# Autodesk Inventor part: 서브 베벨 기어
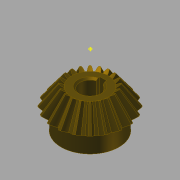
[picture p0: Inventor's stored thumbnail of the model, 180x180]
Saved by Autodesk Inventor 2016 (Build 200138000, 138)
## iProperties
Created: 2014-10
Part Number: 서브 베벨 기어
Material: 강철, 탄소
Document SubType Name: Modeling
Designer: KYOUNG IL JANG
Categories: <?xml version="1.0" encoding="UTF-16"?> <MemberInstance><Categories><FamilyTemplate><FamilyTemplateParameter ValueType="xs:double" Id="1" ObjectReferenceKey="da
Mass: 135.037 g
Surface Area: 63.6518 cm^2
Volume: 17.1585 cm^3
Density: 7.87 g/cm^3
Appearance: 얼룩무늬
CustomPartVersion: 1
Author: SeoGD™ [www.esajin.kr]
Revision Number: 1
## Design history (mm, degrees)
node "맨 위 점"
node "메쉬 평면2"
sketch "톱니 본체 스케치"
  geometry: L1 (0, 0)-(18.003, -31.331); L2 (18.003, -31.331)-(21.664, -28.891); L3 (21.664, -28.891)-(0, 0); L4 (20, -30)-(0, 0); L5 (10.813, -18.818)-(13.012, -17.352); L6 (18.003, -31.331)-(10.813, -18.818); L7 (21.664, -28.891)-(13.012, -17.352); L8 (0, -39.387)-(0, 6.564) reference; L9 (0, -30)-(21.664, -30)
  constraints: 16 end point, 4 point on line, 3 perpendicular, 2 collinear, 1 horizontal alignment, 1 vertical alignment
  dimensions: "d0" = 40 diameter of L4.start L8 (= da_de); "d1" = 36.00616 diameter of L1.end L8 (= da_dfe); "d2" = 43.3282 diameter of L2.end L8 (= da_dae); "d3" = 14.4 distance between parallel lines of L2 L5 (= da_b); "d4" = 28.8906 vertical distance of L2.end L1.start (= da_ve)
revolve "톱니 본체" sketch "톱니 본체 스케치" stored, may be unused: angle "d5" = 90 deg
node "시작점"
node "톱니 평면"
sketch "시작 스케치"
  geometry: L1 (0, -23.505)-(0, 10.645) reference; L2 (-0.834, -2.928)-(0.834, -2.928); A1 r 8.898 centre (-9.698, -3.713) between (-0.834, -2.928) and (-3.903, 3.04); A2 r 8.898 centre (9.698, -3.713) between (3.903, 3.04) and (0.834, -2.928); A3 r 27.357 centre (0, -24.037) between (3.903, 3.04) and (-3.903, 3.04); 1 further point
  constraints: 6 point on circle, 3 centre point, 3 symmetric about line, 2 end point, 1 coincident, 1 perpendicular, 1 other
  dimensions: "d7" = 8.89846 radius of A1 (= fd_rr); "d8" = 9.69794 horizontal distance of point (0, -24.037) A1.centre (= fd_x); "d9" = 20.32439 vertical distance of point (0, -24.037) A1.centre (= fd_y); "d57" = 27.35701 radius of A3 (= 0.5 x fd_dva + 0.3 x da_he); "d58" = 21.10901 distance from line of A3.centre L2 (= 0.5 x fd_dva - 1.12 x da_he)
node "끝점"
  node "끝 평면"
sketch "3D 스케치 오른쪽"
  node "Helical Curve Right" dims "d65" = 229.90621 (computed from da_dm, da_delta, da_beta), "d66" = 31.5, "d67" = 40 (= da_de), "d68" = -5.88003 (= -da_delta), "d69" = 12.16458 (computed from fd_loft, da_delta)
node "끝 평면 오른쪽"
sketch "끝 스케치 오른쪽"
  geometry: L1 (0, -22.649)-(0, 12.15) reference; L2 (-0.497, -1.72)-(0.497, -1.72); A1 r 5.299 centre (-5.775, -2.187) between (-0.497, -1.72) and (-2.324, 1.834); A2 r 5.299 centre (5.775, -2.187) between (2.324, 1.834) and (0.497, -1.72); A3 r 16.291 centre (0, -14.29) between (2.324, 1.834) and (-2.324, 1.834); 1 further point
  constraints: 6 point on circle, 3 centre point, 3 symmetric about line, 2 end point, 1 coincident, 1 perpendicular, 1 other
  dimensions: "d70" = 5.77526 horizontal distance of A3.centre A1.centre (computed from fd_x, fd_ratio); "d71" = 12.10346 vertical distance of point (0, -14.29) A1.centre (computed from fd_y, fd_ratio); "d72" = 5.29916 radius of A1 (computed from fd_rr, fd_ratio); "d73" = 12.57071 distance from line of point (0, -14.29) L2 (computed from d58, fd_ratio); "d74" = 16.29149 radius of A3 (computed from d57, fd_ratio)
feature "로프트 오른쪽" sketch "끝 스케치 오른쪽" dims "d75" = 0, "d77" = 0, "d79" = 0, "d80" = 90 deg, "d85" = 20, "d92" = 90 deg, "d93" = 90 deg, "da_teethtype" = 0 [user parameter]
sketch "3D 스케치 왼쪽"
  node "Helical Curve Left" dims "d26" = 229.90621 (computed from da_dm, da_delta, da_beta), "d27" = 12.16458 (computed from fd_loft, da_delta), "d28" = 40 (= da_de), "d29" = -5.88003 (= -da_delta)
node "끝 평면 왼쪽"
sketch "끝 스케치 왼쪽" dims "d56" = 10.82768 (derived)
  geometry: L1 (0, -35.087)-(0, 18.089) reference; L2 (-0.497, -1.716)-(0.497, -1.716); A1 r 5.299 centre (-5.775, -2.183) between (-0.497, -1.716) and (-2.324, 1.838); A2 r 5.299 centre (5.775, -2.183) between (2.324, 1.838) and (0.497, -1.716); A3 r 16.291 centre (0, -14.287) between (2.324, 1.838) and (-2.324, 1.838); 2 further points; 1 other entity
  constraints: 6 point on circle, 3 centre point, 3 symmetric about line, 2 end point, 1 coincident, 2 other
  dimensions: "d30" = 5.29916 radius of A1 (computed from fd_rr, fd_ratio); "d31" = 5.77526 horizontal distance of point (0, -14.287) A1.centre (computed from fd_x, fd_ratio); "d32" = 12.10346 vertical distance of A1.centre point (0, -14.287) (computed from fd_y, fd_ratio); "d61" = 16.29149 radius of A3 (computed from d57, fd_ratio); "d62" = 12.57071 distance from line of point (0, -14.287) L2 (computed from d58, fd_ratio)
feature "로프트 왼쪽" sketch "끝 스케치 왼쪽" dims "d35" = 0, "d37" = 0, "d39" = 0, "d40" = 90 deg, "d84" = 10, "d90" = 90 deg, "d91" = 90 deg, "da_teethtype" = 0 [user parameter]
sketch "본체 스케치"
  geometry: L1 (0, -35.038)-(0, -19.531) reference; L2 (18.003, -31.331)-(10.813, -18.818) reference; L3 (10.813, -18.818)-(0, -18.818); L4 (18.003, -31.331)-(0, -31.331)
  constraints: 4 end point, 2 perpendicular, 2 point on line
revolve "본체 고정" sketch "본체 스케치" stored, may be unused: angle "d46" = 90 deg
feature "피치 지름" dims angle "d47" = 90 deg
sketch "스케치8"
  geometry: C1 r 17 at (0, 0); 1 further point
  constraints: 1 centre point, 1 coincident
  dimensions: "d94" = 34 diameter of C1
extrude "돌출1" join sketch "스케치8" distance "d95" = 10; taper "d96" = 0 deg
sketch "스케치9"
  geometry: 1 further point
hole "구멍1" sketch "스케치9" at (0, 0) diameter "d97" = 12; stored, may be unused: countersink angle "d101" = 90 deg, drill point angle "d103" = 118 deg; dims "d98" = 6, "d99" = 4, "d100" = 2, "d102" = 8
sketch "스케치10"
  geometry: 1 further point
sketch "스케치11"
  geometry: 1 further point
sketch "스케치12"
  geometry: L1 (-2, 5.657)-(-2, 7.8); L2 (-2, 7.8)-(2, 7.8); L3 (2, 7.8)-(2, 5.657); A1 r 6 centre (0, 0) between (-2, 5.657) and (2, 5.657) reference; 1 further point
  constraints: 6 end point, 2 parallel, 2 point on circle, 1 perpendicular, 1 vertical
  dimensions: "d104" = 4 distance of L1.end L2.end; "d105" = 13.8 dimension on A1 L2
extrude "돌출2" cut sketch "스케치12" stored distance "d106" = 7; taper "d107" = 0 deg
chamfer "모따기1" distance "d108" = 1; stored, may be unused: second distance "d109" = 2, angle "d110" = 45 deg
body "Solid1"
feature "로프트" dims "d17" = 0, "d18" = 90 deg, "d19" = 0, "d20" = 90 deg, "d89" = 0, "da_teethtype" = 0 [user parameter]
pattern_circular "원형 패턴" dims angle "d22" = 360 deg, "d88" = 0, "da_teethtype" = 0 [user parameter]
pattern_circular "원형 패턴 오른쪽" dims angle "d82" = 360 deg, "da_teethtype" = 0 [user parameter]
pattern_circular "원형 패턴 왼쪽" dims angle "d42" = 360 deg, "da_teethtype" = 0 [user parameter]
sketch "끝 스케치"
  geometry: L1 (0, -15.359)-(0, 6.983) reference; L2 (-0.497, -1.72)-(0.497, -1.72); A1 r 5.299 centre (-5.775, -2.187) between (-0.497, -1.72) and (-2.324, 1.834); A2 r 5.299 centre (5.775, -2.187) between (2.324, 1.834) and (0.497, -1.72); A3 r 16.291 centre (0, -14.29) between (2.324, 1.834) and (-2.324, 1.834); 1 further point
  constraints: 6 point on circle, 3 centre point, 3 symmetric about line, 2 end point, 1 coincident, 1 other
  dimensions: "d12" = 5.29916 radius of A1 (computed from fd_rr, fd_ratio); "d15" = 5.77526 horizontal distance of A1.centre point (0, -14.29) (computed from fd_x, fd_ratio); "d16" = 12.10346 vertical distance of A1.centre point (0, -14.29) (computed from fd_y, fd_ratio); "d59" = 16.29149 radius of A3 (computed from d57, fd_ratio); "d60" = 12.57071 distance from line of A3.centre L2 (computed from d58, fd_ratio)
sketch "Sketch6"
  geometry: L1 (20, -30)-(0, 0) reference; L2 (0, -37.8)-(0, 6.3) reference
body "Srf1"
other parameters: "da_b" = 14.4 [user parameter; used in 2 equation terms], "da_de" = 40 [user parameter; used in 4 equation terms], "da_dae" = 43.3282 [user parameter; used in 2 equation terms], "da_dfe" = 36.00616 [user parameter; used in 1 equation term], "da_le" = 36.05551 [user parameter; used in 1 equation term], "da_omega" = 90 deg [user parameter; used in 1 equation term], "da_beta" = 0 [user parameter; used in 2 equation terms], "da_delta" = 5.88003 [user parameter; used in 8 equation terms], "da_alpha" = 20 deg [user parameter; used in 2 equation terms], "da_he" = 4.4 [user parameter; used in 4 equation terms], "da_ve" = 28.8906 [user parameter; used in 1 equation term], "fd_dv" = 48.07402 (computed from da_de, da_delta) [user parameter; used in 1 equation term], "fd_dva" = 52.07402 (computed from da_dae, da_delta) [user parameter; used in 3 equation terms], "fd_dvb" = 45.1748 (computed from fd_dv, da_alpha) [user parameter; used in 2 equation terms], "da_zv" = 240.37008 [user parameter; used in 1 equation term], "fd_loft" = 14.62 (= da_b + 0.05 x da_he) [user parameter; used in 4 equation terms], "fd_ratio" = 5.95514 (computed from da_le, fd_loft) [user parameter; used in 15 equation terms], "fd_rr" = 8.89846 (computed from fd_dd, fd_dvb) [user parameter; used in 6 equation terms], "fd_angle" = 0.66075 (computed from da_zv) [user parameter; used in 4 equation terms], "fd_x1" = 1.58709 (computed from da_dvw, fd_angle) [user parameter; used in 1 equation term], "fd_y1" = 23.98456 (computed from da_dvw, fd_angle) [user parameter; used in 1 equation term], "fd_x2" = 8.11084 (computed from fd_rr, fd_angle2, fd_angle) [user parameter; used in 1 equation term], "fd_y2" = 3.66016 (computed from fd_rr, fd_angle2, fd_angle) [user parameter; used in 1 equation term], "fd_x" = 9.69794 (= fd_x1 + fd_x2) [user parameter; used in 4 equation terms], "fd_y" = 20.32439 (= fd_y1 - fd_y2) [user parameter; used in 4 equation terms], "fd_angle2" = 3.57832 (computed from fd_dvb, fd_dd, da_alpha) [user parameter; used in 2 equation terms], "fd_dd" = 48.55402 (= fd_dva - 0.8 x da_he) [user parameter; used in 2 equation terms], "da_dvw" = 48.07402 [user parameter; used in 2 equation terms], "d11" = 14.62 (= fd_loft), "da_dm" = 32.01232 [user parameter; used in 2 equation terms], "da_x" = 0 [user parameter], "da_m" = 2 [user parameter], "d48" = 0, "d49" = 0, "d50" = 90 deg (= da_omega), "d51" = 9 deg (computed from da_z), "d52" = 0, "d53" = 0, "d54" = 0
